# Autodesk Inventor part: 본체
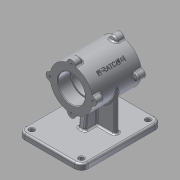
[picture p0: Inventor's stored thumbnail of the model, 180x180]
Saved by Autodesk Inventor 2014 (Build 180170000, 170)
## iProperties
Created: 2015-12
Part Number: 본체
Material: 알루미늄 6061
Document SubType Name: Modeling
Designer: L-10
Density: 2.71 g/cm^3
Appearance: 알루미늄 - 평지
Mass: 1164.68 g
Surface Area: 816.39 cm^2
Volume: 429.772 cm^3
Author: L-10
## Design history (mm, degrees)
sketch "스케치1"
  geometry: L1 (37, 42.5)-(0, 42.5); L2 (0, 42.5)-(0, 0); L3 (0, 0)-(37, 0); L4 (37, 0)-(37, 42.5); 1 further point
  constraints: 8 end point, 2 parallel, 1 coincident, 1 horizontal, 1 perpendicular
  dimensions: "d2" = 74 diameter of L4 L2; "d3" = 42.5 distance of L3.end L1.start
revolve "회전1" sketch "스케치1" stored, may be unused: angle "d4" = 90 deg
hole "구멍1" diameter "d7" = 42; stored, may be unused: countersink angle "d11" = 90 deg, drill point angle "d13" = 0 deg; dims "d5" = 10, "d6" = 10, "d8" = 6, "d9" = 47, "d10" = 22, "d12" = 42.5
sketch "스케치2"
  geometry: L1 (-37, 42.5)-(37, 42.5) reference; L2 (37, 42.5)-(37, 0) reference; L3 (37, 42.5)-(44, 42.5); L4 (44, 42.5)-(44, 30.048); L5 (44, 30.048)-(37, 27.5); L6 (37, 42.5)-(37, 27.5); 1 further point
  constraints: 8 end point, 2 perpendicular, 1 collinear, 1 point on line
  dimensions: "d14" = 110 deg angle of L2 L5; "d15" = 15 distance from line of L5.end L3; "d16" = 7 distance of L2.start L3.end
revolve "회전2" sketch "스케치2" stored, may be unused: angle "d17" = 90 deg
hole "구멍3" diameter "d29" = 3.242; stored, may be unused: countersink angle "d33" = 90 deg, drill point angle "d35" = 118 deg; dims "d27" = 10, "d28" = 10, "d30" = 9, "d31" = 47, "d32" = 22, "d34" = 11
fillet "모깎기1" dims "d36" = 3
node "작업 평면1"
sketch "스케치3"
  geometry: L1 (55, 80)-(-55, 80); L2 (-55, 80)-(-55, -60); L3 (-55, -60)-(55, -60); L4 (55, -60)-(55, 80); 2 further points
  constraints: 8 end point, 2 parallel, 1 horizontal, 1 midpoint, 1 perpendicular, 1 vertical alignment
  dimensions: "d41" = 140 distance of L3.end L1.start; "d42" = 110 distance of L2.end L3.end; "d43" = 80 distance from line of point (0, 0) L1
extrude "돌출1" join sketch "스케치3" distance "d44" = 10; taper "d45" = 0 deg
sketch "스케치4"
  geometry: L1 (-37, -4)-(37, -4); L2 (37, -4)-(37, 4); L3 (37, 4)-(-37, 4); L4 (-37, 4)-(-37, -4); 3 further points
  constraints: 8 end point, 2 midpoint, 2 parallel, 1 horizontal, 1 horizontal alignment, 1 perpendicular, 1 vertical alignment
  dimensions: "d46" = 8 distance of L3.end L1.start; "d47" = 74 distance of L2.end L3.end
extrude "돌출2" join sketch "스케치4" stored distance "d48" = 10; taper "d49" = 0 deg
sketch "스케치5"
  geometry: L1 (-37, 25.399)-(-37, -25.399) reference; L2 (-70, 4)-(0, 4) reference; L3 (-70, -60)-(-70, 80) reference; L4 (-37, 20.948)-(-70, 25); 1 further point
  constraints: 2 end point, 2 point on line
  dimensions: "d50" = 97 deg angle of L3 L4; "d51" = 25 vertical distance of point (0, 0) L4.end
feature "리브1" sketch "스케치5" dims "d52" = 1, "d53" = 12, "d54" = 0, "d55" = 0, "d56" = 1, "d57" = 1
fillet "모깎기2" dims "d58" = 12
sketch "스케치6"
  geometry: L1 (-55, 48)-(-55, -68) reference; L2 (43, 60)-(-43, 60) reference; L3 (-43, -68)-(43, -68); L4 (43, -68)-(43, 48); L5 (43, 48)-(-43, 48); L6 (-43, 48)-(-43, -68); 9 further points
  constraints: 8 end point, 4 coincident, 4 midpoint, 2 parallel, 1 horizontal, 1 horizontal alignment, 1 perpendicular, 1 vertical alignment
  dimensions: "d59" = 116 distance of L5.end L3.start; "d60" = 86 distance of L3.start L3.end
hole "구멍4" sketch "스케치6" at (-43, -68), (43, -68), (43, 48), (-43, 48) diameter "d61" = 8; stored, may be unused: countersink angle "d65" = 90 deg, drill point angle "d67" = 0 deg; dims "d62" = 9, "d63" = 47, "d64" = 22, "d66" = 11
chamfer "모따기1" distance "d68" = 1; stored, may be unused: second distance "d69" = 2, angle "d70" = 45 deg
chamfer "모따기2" distance "d71" = 1; stored, may be unused: second distance "d72" = 2, angle "d73" = 45 deg
chamfer "모따기3" distance "d74" = 1; stored, may be unused: second distance "d75" = 2, angle "d76" = 45 deg
chamfer "모따기4" distance "d77" = 1; stored, may be unused: second distance "d78" = 2, angle "d79" = 45 deg
fillet "모깎기3" dims "d80" = 3
fillet "모깎기4" dims "d81" = 3
sketch "스케치7"
  geometry: L1 (0, 0)-(26.163, 26.163); L2 (-77, 0)-(77, 0) reference; A1 r 37 centre (0, 0) between (35.863, 9.104) and (9.104, 35.863) reference; 1 further point
  constraints: 2 end point, 1 coincident, 1 point on circle
  dimensions: "d82" = 45 deg angle of L2 L1
node "작업 평면2"
sketch "스케치8"
  geometry: L1 (-18.921, 42.5)-(18.921, 42.5) reference; 2 further points
  constraints: 1 coincident, 1 other
  dimensions: "d83" = 42.5 distance from line of point (0, 0) L1
feature "엠보싱1" sketch "스케치8" dims "d2" = 74, "d3" = 42.5, "d84" = 1, "d85" = 0
chamfer "모따기5" distance "d86" = 1; stored, may be unused: second distance "d87" = 2, angle "d88" = 45 deg
chamfer "모따기6" distance "d89" = 1; stored, may be unused: second distance "d90" = 2, angle "d91" = 45 deg
fillet "모깎기5" dims "d92" = 0.3
node "솔리드1"
pattern_circular "원형 패턴1" dims "d38" = 360 deg
mirror "대칭1"
mirror "대칭2"
